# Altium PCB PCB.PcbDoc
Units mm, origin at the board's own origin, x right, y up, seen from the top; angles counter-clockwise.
Board outline 41 x 25.36 mm, 2 copper layers (TOP, BOTTOM), stack 1.586 mm thick; 37 components, 21 nets, 97 pads, 42 vias.
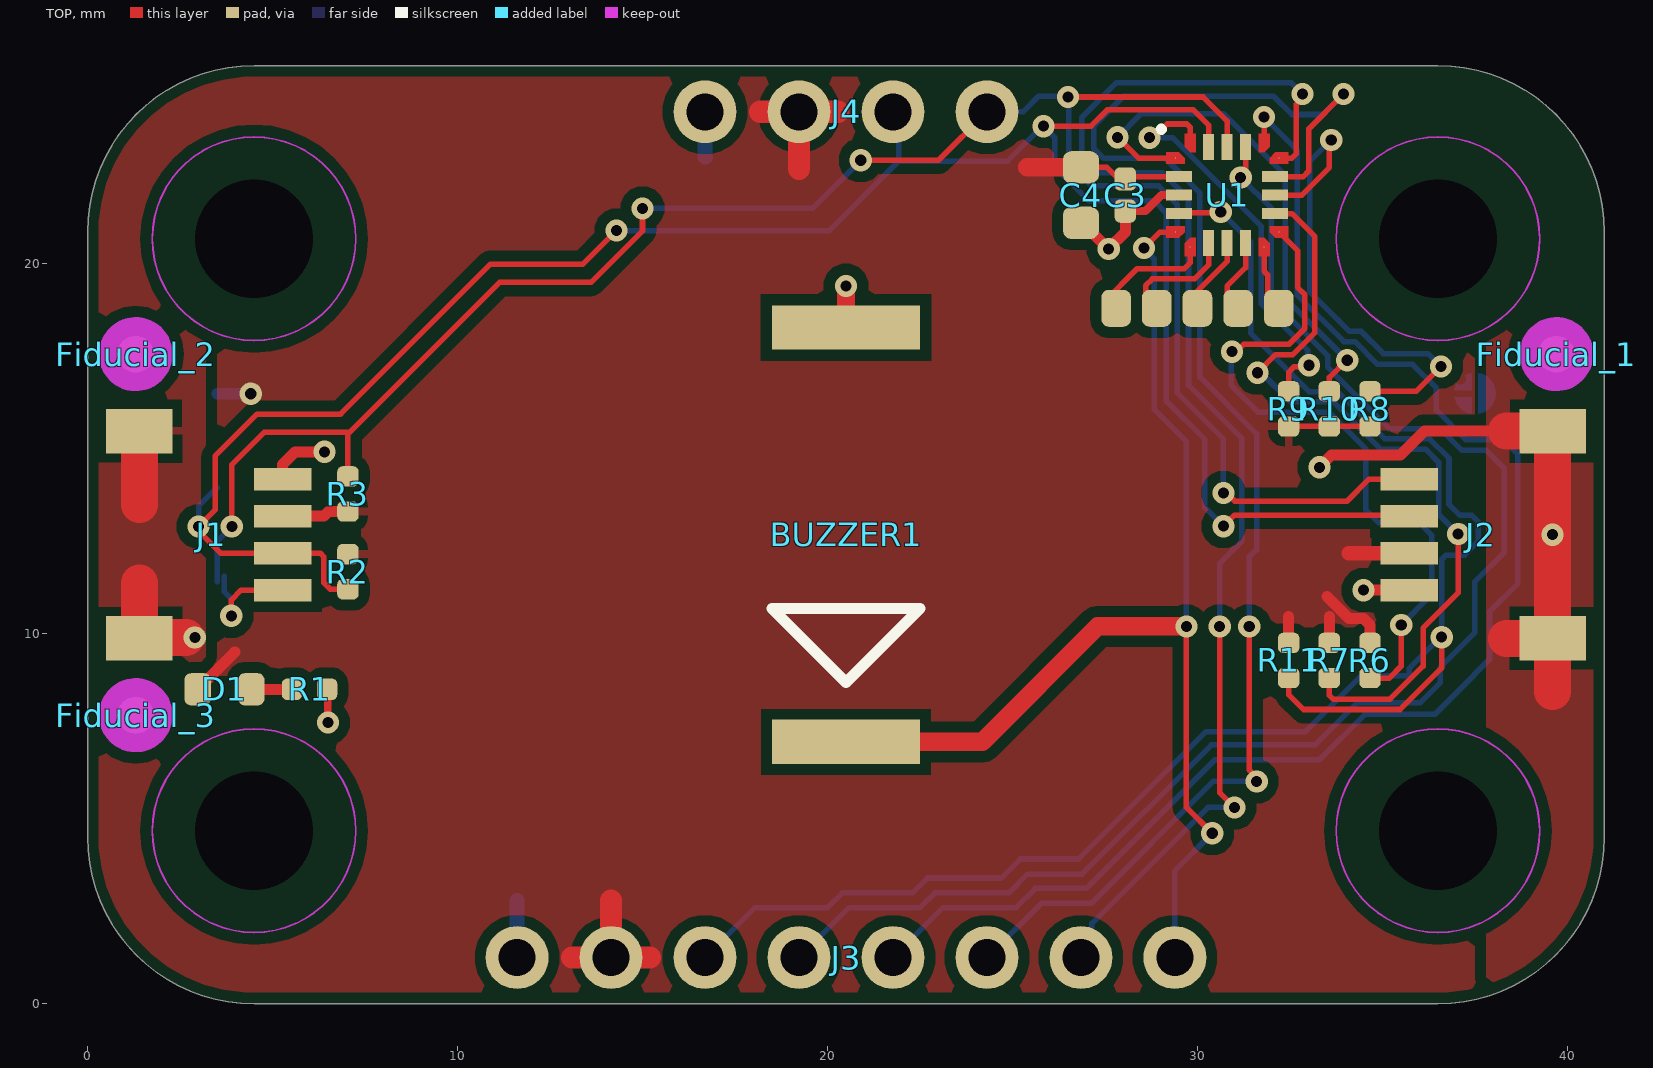
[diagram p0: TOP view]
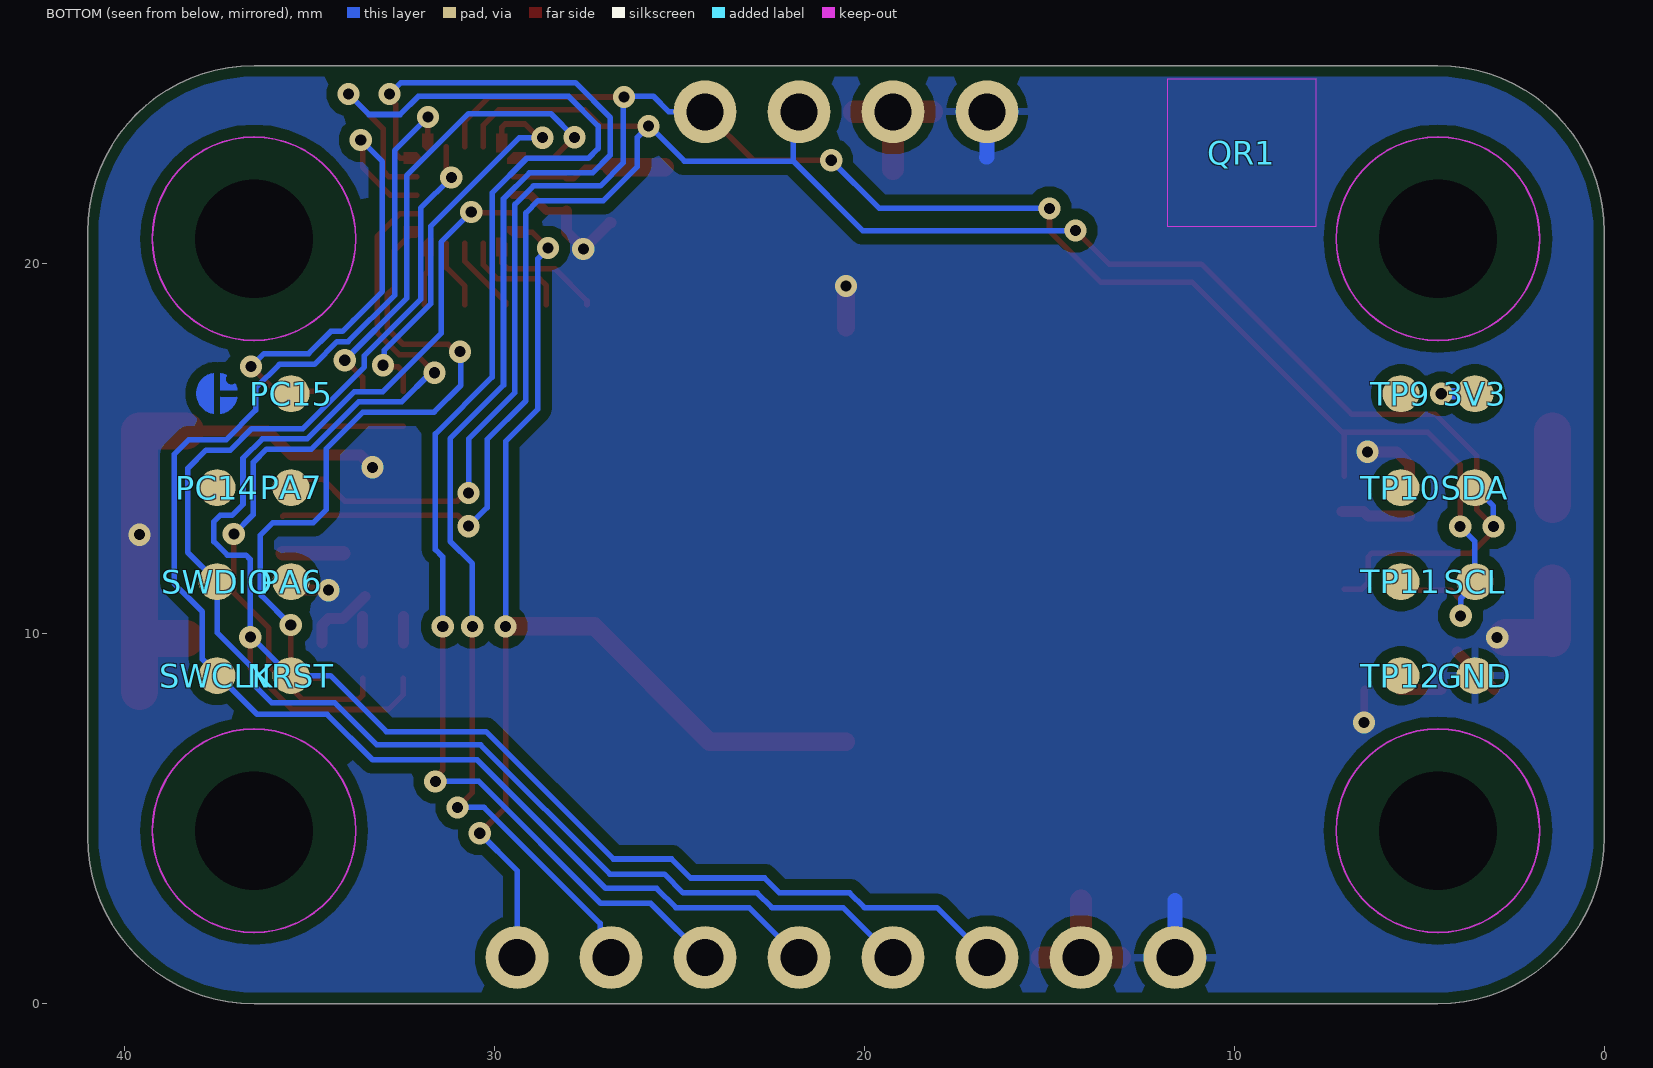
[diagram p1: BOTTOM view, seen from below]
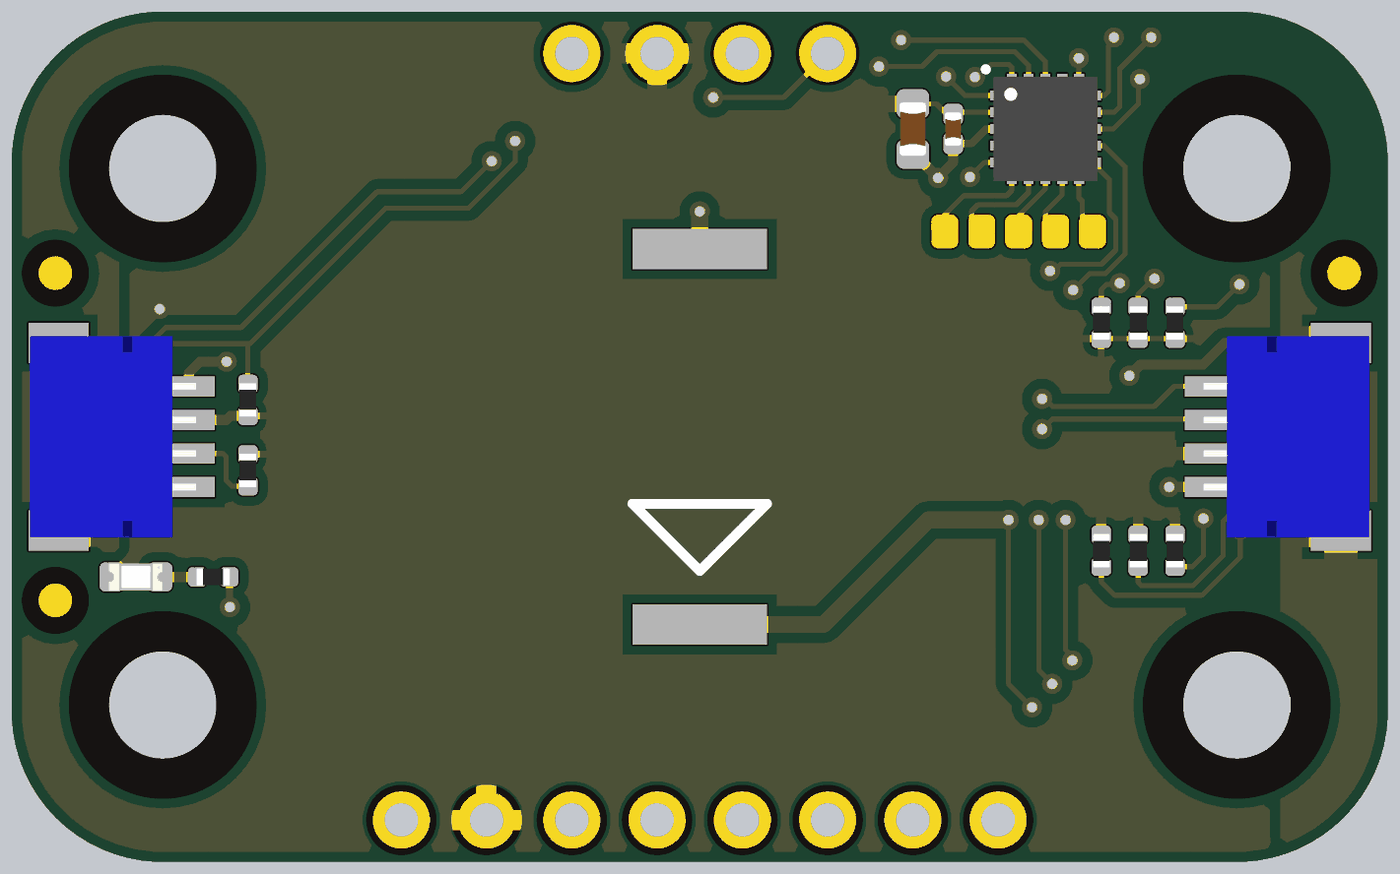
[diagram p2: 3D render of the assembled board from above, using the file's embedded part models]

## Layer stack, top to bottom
Top Solder: solder mask 0.01, Solder Resist, Dk 3.5
TOP: signal copper 0.018
Dielectric: core 1.55, FR-4, Dk 4.8
BOTTOM: signal copper 0.018
Bottom Solder: solder mask 0.01, Solder Resist, Dk 3.5

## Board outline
0,4.5 ccw(c4.5,4.5) 4.5,0 36.5,0 ccw(c36.5,4.5) 41,4.5 41,20.86 ccw(c36.5,20.86) 36.5,25.36 4.5,25.36 ccw(c4.5,20.86) 0,20.86

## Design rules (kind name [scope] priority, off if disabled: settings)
BoardOutlineClearance Mousebites [(ObjectKind = 'Pad') And (Name = 'Free-MOUSEBITE')] p1: gap=0 ignorepadtopadclearanceinfootprint=FALSE
BoardOutlineClearance Silks [(OnLayer('Top Overlay') OR OnLayer('Bottom Overlay'))] p2: gap=0 ignorepadtopadclearanceinfootprint=FALSE
BoardOutlineClearance [All] p3: gap=0.3 ignorepadtopadclearanceinfootprint=FALSE
Clearance COPPER_0.3mm [All] p1: gap=0.127 ignorepadtopadclearanceinfootprint=FALSE except(0.3: Arc-Fill Arc-Poly Arc-Region Track-Fill Track-Poly Track-Region SMDPad-Fill SMDPad-Poly SMDPad-Region THPad-Fill THPad-Poly THPad-Region Via-Fill Via-Poly Via-Region Fill-Fill Fill-Poly Fill-Region Poly-Poly Poly-Region Region-Region)
Clearance "Generic clearance 0.15mm" [All] p2: gap=0.15 ignorepadtopadclearanceinfootprint=FALSE
ComponentClearance [All] p1: gap=0.2 collisioncheckmode=3 verticalgap=0 showdistances=TRUE
DiffPairsRouting USB [InDifferentialPairClass('USB')] p1: maxlimit=0.15 minlimit=0.15 mostfreqgap=0.15 toplayer_minwidth=0.15 toplayer_maxwidth=0.21 toplayer_prefwidth=0.2 bottomlayer_minwidth=0.15 bottomlayer_maxwidth=0.21 bottomlayer_prefwidth=0.2 impedanceprofiledriven=TRUE impedanceprofileid={E6B00C31-4C8E-439C-824F-D2B2CDC26F9C} impedanceprofilevalue=90.000000 maxuncoupledlength=12.7
Height [All] p1: minheight=0 maxheight=30 prefheight=12.7
HoleSize [All] p1: absolutevalues=TRUE maxlimit=30 minlimit=0.3 maxpercent=80.000 minpercent=20.000
HoleToHoleClearance [All] p1: gap=0.25 allowstackedmicrovias=FALSE
MinimumAnnularRing [All] p1: minimumring=0.15
PlaneConnect [All] p1: pad.planeconnectstyle=Relief pad.reliefexpansion=0.508 pad.reliefentries=4 pad.reliefconductorwidth=0.254 pad.reliefairgap=0.254 via.planeconnectstyle=Direct via.reliefexpansion=0.508 via.reliefentries=4 via.reliefconductorwidth=0.254 via.reliefairgap=0.254
PolygonConnect [All] p1: thpad.connectstyle=Relief thpad.reliefconductorwidth=0.2 thpad.reliefentries=4 thpad.polygonreliefangle="90 Angle" thpad.airgapwidth=0.254 smdpad.connectstyle=Relief smdpad.reliefconductorwidth=0.2 smdpad.reliefentries=4 smdpad.polygonreliefangle="90 Angle" smdpad.airgapwidth=0.254 via.connectstyle=Direct via.reliefconductorwidth=0.254 via.reliefentries=4 via.polygonreliefangle="90 Angle" via.airgapwidth=0.254
RoomDefinition TOP [InComponentClass('TOP')] p1: confinementstyle=ConfineIn formatcopy=TRUE lockcomponents=FALSE outline 42.8,6 51.9,6 51.9,19.2 42.8,19.2
RoutingVias StandardVias [All] p1: holewidth=0.3 width=0.6 viastyle="Through Hole" minholewidth=0.3 minwidth=0.6 maxholewidth=0.3 maxwidth=0.6
SMDToCorner [All] p1: distance=39370
SilkToSilkClearance [All] p1: silktosilkclearance=0.2
SilkToSolderMaskClearance [IsPad] p1: minsilkscreentomaskgap=0.15 clearancetoexposedcopper=TRUE
SolderMaskExpansion VIAtented [IsVia] p1: expansion=0.102 istentingtop=TRUE
SolderMaskExpansion [All] p2: expansion=0.05 istentingtop=FALSE
UnConnectedPin [All] p1:
UnRoutedNet [not WithinRoom('K36')] p1: checkbadconnections=TRUE
ViasUnderSMD [All] p1: allowed=FALSE
Width StandardTraces [All] p1: maxlimit=5 minlimit=0.15 preferedwidth=0.15 minimp=50.000000 maximp=50.000000 favimp=50.000000
21 further rules are at their usual default settings.

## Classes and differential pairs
component class TOP: 3V3 BUZZER1 D1 Fiducial_1 Fiducial_2 Fiducial_3 GND J1 J2 J3 J4 NRST PA6 PA7 PC14 PC15 QR1 R1 SCL SDA SWCLK SWDIO TP9 TP10 TP11 TP12
component class U_MICROCONTROLLER: C3 C4 R2 R3 R6 R7 R8 R9 R10 R11 U1

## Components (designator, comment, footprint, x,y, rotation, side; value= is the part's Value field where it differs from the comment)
3V3 "Test point 1.00mm" TP-1.00MM 3.5,16.49 r90 bottom
BUZZER1 "PKLCS1212E4001-R1" PKLCS1212E4001-R1 20.5,12.68 r180 top
C3 "0402B104K160CT" CAP-0402 28.05,21.86 r270 top value=100nF
C4 "GRM188R61C475KAAJD" CAP-0603 26.85,21.86 r90 top value=4.7µF
D1 "HSMG-C190" LEDC1608X80N-AK 3.7,8.5 r180 top
Fiducial_1 "Fiducial mark 1mm" "Fiducial mark 1mm-Footprint-1" 39.7,17.56 r270 top
Fiducial_2 "Fiducial mark 1mm" "Fiducial mark 1mm-Footprint-1" 1.3,17.56 r270 top
Fiducial_3 "Fiducial mark 1mm" "Fiducial mark 1mm-Footprint-1" 1.3,7.8 r270 top
GND "Test point 1.00mm" TP-1.00MM 3.5,8.87 r90 bottom
J1 "SM04B-SRSS-TB(LF)(SN)" SM04B-SRSS-TB(LF)(SN)-Footprint-1 3.337,12.68 r90 top locked
J2 "SM04B-SRSS-TB(LF)(SN)" SM04B-SRSS-TB(LF)(SN)-Footprint-1 37.663,12.68 r270 top locked
J3 "HEADER TH 2.54mm VERT. 1x008POS" "PIN HEADER 2.54mm VERT. 1x8POS" 20.5,1.25 r0 top
J4 "HEADER TH 2.54mm VERT. 1x004POS" "PIN HEADER 2.54mm VERT. 1x4POS-Footprint-1" 20.5,24.11 r0 top
NRST "Test point 1.00mm" TP-1.00MM 35.5,8.87 r180 bottom
PA6 "Test point 1.00mm" TP-1.00MM 35.5,11.41 r180 bottom
PA7 "Test point 1.00mm" TP-1.00MM 35.5,13.95 r180 bottom
PC14 "Test point 1.00mm" TP-1.00MM 37.5,13.95 r180 bottom
PC15 "Test point 1.00mm" TP-1.00MM 35.5,16.49 r180 bottom
QR1 "QR CODE 4x4mm" "QR CODE 4x4mm" 9.8,23 r180 bottom
R1 "CRCW04021K00FKEDC" RES-0402 6,8.5 r180 top value=1k
R2 "RC0402FR-074K7L" RES-0402 7.039,11.68 r90 top value=4.7k
R3 "RC0402FR-074K7L" RES-0402 7.039,13.78 r270 top value=4.7k
R6 "RC0402FR-074K7L" RES-0402 34.663,9.28 r270 top value=4.7k
R7 "RC0402FR-074K7L" RES-0402 33.563,9.28 r270 top value=4.7k
R8 "RC0402FR-074K7L" RES-0402 34.663,16.08 r90 top value=4.7k
R9 "RC0402FR-074K7L" RES-0402 32.463,16.08 r90 top value=4.7k
R10 "RC0402FR-074K7L" RES-0402 33.563,16.08 r90 top value=4.7k
R11 "RC0402FR-074K7L" RES-0402 32.463,9.28 r270 top value=4.7k
SCL "Test point 1.00mm" TP-1.00MM 3.5,11.41 r90 bottom
SDA "Test point 1.00mm" TP-1.00MM 3.5,13.95 r90 bottom
SWCLK "Test point 1.00mm" TP-1.00MM 37.5,8.87 r180 bottom
SWDIO "Test point 1.00mm" TP-1.00MM 37.5,11.41 r180 bottom
TP9 "Test point 1.00mm" TP-1.00MM 5.5,16.49 r0 bottom
TP10 "Test point 1.00mm" TP-1.00MM 5.5,13.95 r0 bottom
TP11 "Test point 1.00mm" TP-1.00MM 5.5,11.41 r0 bottom
TP12 "Test point 1.00mm" TP-1.00MM 5.5,8.87 r0 bottom
U1 "STM32C011F4U6TR" UFQFPN20 30.8,21.86 r0 top

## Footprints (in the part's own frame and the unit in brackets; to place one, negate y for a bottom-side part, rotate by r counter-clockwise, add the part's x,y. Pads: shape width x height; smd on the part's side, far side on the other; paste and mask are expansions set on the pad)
CAP-0402 [mm] "Chip Capacitor, 2-Leads, Body  0402 (in) 1005 (mm), IPC Medium Density"
  rrect52% 0.63x0.58 smd mask+0.05: 1(-0.435,0) 2(0.435,0)
  body extent -0.5,-0.25 0.5,0.25, height 0.5
CAP-0603 [mm] "Chip Capacitor, Body 0603 imperial,1.6x0.8mm, IPC High Density"
  rrect51% 0.87x0.97 smd mask+0.05: 1(-0.75,0) 2(0.75,0)
  body extent -0.8,-0.4 0.8,0.4, height 0.8
"Fiducial mark 1mm-Footprint-1" [mm]
  round 1 smd paste-10 mask+0.5: 1(0,0)
  TOP keep-out circle w1: c0,0 r0.5
LEDC1608X80N-AK [mm]
  rrect50% 0.72x0.87 smd: A(0.725,0) C(-0.725,0)
  body extent -0.8,-0.4 0.8,0.4, height 0.79
"PIN HEADER 2.54mm VERT. 1x4POS-Footprint-1" [mm]
  round 1.7 hole 1 mask+0.1: 1(-3.81,0) 2(-1.27,0) 3(1.27,0) 4(3.81,0)
"PIN HEADER 2.54mm VERT. 1x8POS" [mm]
  round 1.7 hole 1 mask+0.2: 1(-8.89,0) 2(-6.35,0) 3(-3.81,0) 4(-1.27,0) 5(1.27,0) 6(3.81,0) 7(6.35,0) 8(8.89,0)
PKLCS1212E4001-R1 [mm]
  rect 4x1.2 smd: 1(0,5.6) 2(0,-5.6)
  silkscreen extent -2,2 2,4, body extent -6,-6 6,6, height 3.03
"QR CODE 4x4mm" [mm]
  TOP keep-out region: -2,2 2,2 2,-2 -2,-2
RES-0402 [mm] "Chip Resistor, 2-Leads, Body  0402 (in) 1005 (mm), IPC Medium Density"
  rrect51% 0.55x0.58 smd mask+0.05: 1(-0.475,0) 2(0.475,0)
  body extent -0.5,-0.25 0.5,0.25, height 0.34
SM04B-SRSS-TB(LF)(SN)-Footprint-1 [mm]
  rect 0.6x1.55 smd mask+0.05: 1(1.5,-1.937) 2(0.5,-1.937) 3(-0.5,-1.937) 4(-1.5,-1.937)
  rect 1.2x1.8 smd mask+0.05: FIX(-2.8,1.938) FIX(2.8,1.938)
  body extent -3,-2.16 3,2.8, height 2.98
TP-1.00MM [mm]
  rrect100% 1x1 smd paste-2.54: X(0,0)
UFQFPN20 [mm] "QFN, 20-Leads, Body 3.00x3.00mm, Pitch 0.50mm, IPC Medium Density"
  round 0.025 smd mask+0.05: 1(-1.4,1) 5(-1.4,-1) 6(-1,-1.4) 10(1,-1.4) 11(1.4,-1) 15(1.4,1) 16(1,1.4) 20(-1,1.4)
  rect 0.7x0.3 smd mask+0.05: 2(-1.3,0.5) 3(-1.3,0) 4(-1.3,-0.5) 12(1.3,-0.5) 13(1.3,0) 14(1.3,0.5)
  rect 0.3x0.7 smd mask+0.05: 7(-0.5,-1.3) 8(0,-1.3) 9(0.5,-1.3) 17(0.5,1.3) 18(0,1.3) 19(-0.5,1.3)
  TOP region: -1.3,-1.15 -1.15,-1 -1.15,-0.85 -1.65,-0.85 -1.65,-1.15
  TOP region: -0.85,-1.65 -1.15,-1.65 -1.15,-1.3 -1,-1.15 -0.85,-1.15
  TOP region: 1.15,-1.65 0.85,-1.65 0.85,-1.15 1,-1.15 1.15,-1.3
  TOP region: 1.65,1.15 1.65,0.85 1.15,0.85 1.15,1 1.3,1.15
  TOP region: 1,1.15 0.85,1.15 0.85,1.65 1.15,1.65 1.15,1.3
  TOP region: -1.15,1 -1.15,0.85 -1.65,0.85 -1.65,1.15 -1.3,1.15
  TOP region: -1.15,1.3 -1,1.15 -0.85,1.15 -0.85,1.65 -1.15,1.65
  TOP region: 1.65,-0.85 1.65,-1.15 1.3,-1.15 1.15,-1 1.15,-0.85
  silkscreen extent -1.8,1.75 -1.75,1.8, body extent -1.55,-1.55 1.55,1.55, height 0.6

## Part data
3V3 GND NRST PA6 PA7 PC14 PC15 SCL SDA SWCLK SWDIO TP9 TP10 TP11 TP12: library part UT0013-A.6, Manufacturer="This is not a component"
BUZZER1: library part S0056-A.2, "BUZZER VDD max 12.5Vpp, max 100mA, min 75dB at 4kHz 12x12x3mm", Manufacturer=Murata
C3: library part C0012-A.15, "CAP CHIP 0402 100nF 10% 16V X7R", Case Code (Imperial)=0402, Dielectric=X7R, Manufacturer=Walsin, Tolerance=10%, Voltage=16V
C4: library part C0054-A.16, "CAP CHIP 0603 4.7uF 10% 16V X5R", Case Code (Imperial)=0603, Dielectric=X5R, Manufacturer=Murata, Manufacturer 3="Samsung Electro-Mechanics", Part number 2=GRM188R61C475KE11D, Part number 3=CL10A475KO8NNNC, Tolerance=10%, Voltage=16V
D1: library part L0009-A.5, "LED SMD 0603 GREEN/568 15mcd 120^", Manufacturer=Broadcom
Fiducial_1 Fiducial_2 Fiducial_3: library part UT0023-A.7, "Fiducial mark 1mm clearance 2mm"
J1 J2: library part J0005-A.2, "CONN JST 4POS SIDE 1MM TIN QWIIC", Manufacturer=JST
J3: library part J0171-A.3
J4: library part J0162-A.5
QR1: library part QR-0001-A.2, "QR CODE 4x4mm on layer 34 (This is not a component)", Manufacturer="This is not a component"
R1: library part R0007-A.24, "RES CHIP 0402 1k 1% 1/16W", Case Code (Imperial)=0402, Manufacturer=Vishay, Power=62.5mW, Temperature Coefficient=100ppm, Tolerance=1%
R2 R3 R6 R7 R8 R9 R10 R11: library part R0013-A.24, "RES CHIP 0402 4k7 1% 1/16W", Case Code (Imperial)=0402, Manufacturer=YAGEO, Power=62.5mW, Temperature Coefficient=200ppm, Tolerance=1%
U1: library part U0363-A.3, "IC Cortex M0, 32b MCU, 32KB Flash, 6KB RAM, VDD 2-3.6V, -40°C to 85°C, QFN20 3x3mm", Manufacturer="ST Microelectronics"

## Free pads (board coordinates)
  rrect50% 0.8x1 smd paste-2539.97: 3V8(28.9,18.8) 3V9(27.8,18.8) 3V9(30,18.8) 3V10(31.1,18.8) 3V10(32.2,18.8)
  round 3 hole 3.2 unplated paste-2539.97 mask+1.3: MH(4.5,4.68) MH(4.5,20.68) MH(36.5,4.68) MH(36.5,20.68)

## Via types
v1: diameter 0.6, hole 0.3, TOP to BOTTOM, tented both sides, 42 vias

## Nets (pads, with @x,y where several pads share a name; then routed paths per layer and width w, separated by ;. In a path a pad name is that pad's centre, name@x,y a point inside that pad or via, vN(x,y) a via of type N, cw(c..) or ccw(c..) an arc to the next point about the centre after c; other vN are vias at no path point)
+3V3: 3V3.X C3.1 C4.2 D1.A J1.2 J2.2 J3.2 J4.2 R2.2 R3.2 R6.1 R7.1 R8.1 R9.1 R10.1 R11.1 U1.2 | length 23
  TOP w0.15: C4.2 27.55,22.61 27.865,22.295 C3.1 28.115,22.36 U1.2 ; R9.1 R10.1 R8.1
  TOP w0.3: D1.A 3.98,9.505 ; J1.2 6.389,13.18 6.514,13.305 R3.2@7.089,13.305 ; R11.1 32.463,10.463 ; 33.5,11.01 34.1,10.41 34.487,10.41 34.663,10.234 R6.1 ; R7.1 33.563,10.463
  TOP w0.4: 34.088,12.18 J2.2
  TOP w0.5: 25.4,22.61 C4.2
  TOP w0.6: 13.1,1.25 J3.2 ; 14.15,2.79 J3.2 ; 15.2,1.25 J3.2 ; 18.18,24.11 J4.2 ; 19.23,22.57 J4.2 ; 20.28,24.11 J4.2
  BOTTOM w0.3: 3V3.X v1(4.41,16.49)
GND: BUZZER1.2 C3.2 C4.1 GND.X J1.1 J1.FIX J2.1 J2.FIX J3.1 J4.1 R1.1 U1.3 | length 34.1
  TOP w0.2: R1.1 6.488,8.488 6.488,7.612 v1(6.5,7.6)
  TOP w0.22: C3.2 28.592,21.425 29.027,21.86 U1.3
  TOP w0.3: J1.1 5.275,14.58 5.614,14.919 v1(6.404,14.919) ; C4.1 26.895,21.11 v1@27.6,20.405 ; v1(27.6,20.4) v1@27.6,20.405 ; C3.2 28.05,20.866 27.6,20.416 v1@27.6,20.405 ; v1(33.3,14.5) 33.628,14.828 35.486,14.828 36.138,15.48 J2.FIX@39.601,15.48 ; v1(34.488,11.18) J2.1
  TOP w0.5: J1.FIX@1.399,9.88 1.419,9.9 v1(2.9,9.9) ; BUZZER1.2 v1(20.5,19.4)
  TOP w1: J1.FIX@1.399,9.88 1.399,11.379 ; 1.399,13.499 J1.FIX@1.399,15.48 ; J1.FIX@1.419,9.9 v1@2.667,9.9 ; 38.353,9.88 J2.FIX@39.601,9.88 ; 38.353,15.48 39.601,15.48 J2.FIX@39.601,9.88 ; 39.601,8.443 J2.FIX@39.601,9.88
  BOTTOM w0.4: J3.1 11.61,2.79 ; J4.1 16.69,22.89 16.7,22.88
  other v1: 39.596,12.68
NetD1_C: D1.C R1.2 | length 1.1
  TOP w0.3: D1.C R1.2
NetU1_6: pad.3V9@27.8,18.8 U1.6 | length 3.3
  TOP w0.15: pad.3V9@27.5,18.9 27.5,19 28.373,19.873 29.644,19.873 29.8,20.028 U1.6
NetU1_7: pad.3V8 U1.7 | length 3
  TOP w0.15: pad.3V8@28.6,18.9 28.6,19.415 28.781,19.596 29.925,19.596 30.3,19.971 U1.7
NetU1_8: pad.3V9@30,18.8 U1.8 | length 2.1
  TOP w0.15: pad.3V9@29.7,18.9 29.7,18.968 30.8,20.068 U1.8
NetU1_9: pad.3V10@31.1,18.8 U1.9 | length 1.9
  TOP w0.15: pad.3V10@30.8,18.9 30.8,19.4 31.3,19.9 U1.9
NetU1_10: pad.3V10@32.2,18.8 U1.10 | length 1.6
  TOP w0.15: U1.10 31.8,19.8 31.9,19.7 pad.3V10@31.9,18.9
PA0_1: BUZZER1.1 J3.8 U1.5 | length 31.9
  TOP w0.15: v1(28.552,20.428) 28.984,20.86 U1.5 ; v1(29.7,10.2) 29.7,5.31 v1(30.4,4.61)
  TOP w0.5: BUZZER1.1 24.18,7.08 27.3,10.2 v1(29.7,10.2)
  BOTTOM w0.15: v1(28.552,20.428) 28.552,20.413 28.828,20.138 28.828,16.072 29.7,15.2 v1(29.7,10.2) ; J3.8 29.39,3.6 v1(30.4,4.61)
PA6_2: R6.2 U1.11 | length 19
  TOP w0.15: v1(30.937,17.626) 31.053,17.626 31.249,17.823 32.466,17.823 32.899,18.255 32.899,19.17 32.705,19.364 32.705,20.355 U1.11 ; R6.2 35.184,8.805 35.508,9.128 v1(35.508,10.241)
  BOTTOM w0.15: v1(30.937,17.626) 30.913,17.602 30.913,16.717 31.636,15.994 33.558,15.994 34.547,15.005 34.547,13.356 34.903,13 36,13 36.33,12.67 36.33,11.13 36.3,11.1 36.3,11.033 v1(35.508,10.241)
PA7_2: R7.2 U1.12 | length 21.4
  TOP w0.15: v1(31.624,17.056) 32.113,17.546 32.581,17.546 33.176,18.141 33.176,20.734 32.55,21.36 U1.12 ; R7.2 33.563,8.337 33.665,8.234 35.203,8.234 36.098,9.129 36.098,10.158 37.054,11.114 37.054,12.689 v1(37.046,12.697)
  BOTTOM w0.15: v1(31.624,17.056) 31.723,17.056 32.509,16.271 33.673,16.271 34.952,14.992 36.162,14.992 36.521,14.632 36.521,13.222 v1(37.046,12.697)
PA8_2: R8.2 U1.13 | length 13.5
  TOP w0.15: U1.13 32.822,21.86 33.567,22.605 33.567,23.3 v1(33.615,23.347) ; R8.2 35.908,16.555 v1(36.579,17.226)
  BOTTOM w0.15: v1(33.615,23.347) 33.029,22.762 33.029,19.258 33.816,18.471 34.114,18.173 34.427,18.173 35.027,17.573 36.231,17.573 v1(36.579,17.226)
PA9_USART1_TX_1: J3.6 U1.14 | length 40.9
  TOP w0.15: v1(31.4,10.2) 31.4,6.323 31.6,6.123 v1(31.6,6.01) ; U1.14 32.86,22.36 33.008,22.508 33.008,23.648 v1(33.95,24.59)
  BOTTOM w0.15: J3.6 25.778,2.718 27.133,2.718 30.425,6.01 v1(31.6,6.01) ; v1(31.4,10.2) 31.4,12.078 31.6,12.278 31.6,15.404 30.067,16.938 30.067,21.917 29.13,22.854 27.463,22.854 27.199,23.118 27.199,23.73 27.998,24.53 32.058,24.53 32.551,24.037 33.397,24.037 v1(33.95,24.59)
PA10_USART1_RX_1: J3.7 U1.15 | length 36.7
  TOP w0.15: v1(30.6,10.2) 30.6,5.71 v1(31,5.31) ; U1.15 32.554,22.86 32.671,22.977 32.671,24.312 32.841,24.482 v1(32.841,24.591)
  BOTTOM w0.15: J3.7 27.147,1.547 27.147,2.172 30.285,5.31 v1(31,5.31) ; v1(30.6,10.2) 30.6,11.9 31.202,12.502 31.202,15.276 29.757,16.72 29.757,21.759 29.056,22.46 27.35,22.46 26.871,22.939 26.871,23.956 27.816,24.9 32.531,24.9 v1(32.841,24.591)
PA13_SWDIO_1: J3.5 SWCLK.X U1.16 | length 39.4
  TOP w0.15: v1@31.744,24.019 v1(31.795,23.968) 31.8,23.963 U1.16
  BOTTOM w0.15: J3.5 23.12,2.6 25.1,2.6 25.618,3.118 26.993,3.118 30.471,6.596 33.296,6.596 34.523,7.823 36.413,7.823 37.48,8.89 37.48,8.899 37.9,9.319 37.9,10.6 38.662,11.362 38.662,14.848 38.266,15.244 37.256,15.244 36.456,16.044 36.456,16.639 35.812,17.282 34.869,17.282 34.255,17.896 33.955,17.896 32.702,19.149 32.702,23.061 v1(31.795,23.968)
PA14_SWCLK_BOOT0_1: J3.4 SWDIO.X U1.17 | length 39.8
  TOP w0.15: v1(31.167,22.336) 31.167,22.429 31.3,22.562 U1.17
  BOTTOM w0.15: J3.4 20.58,2.6 22.5,2.6 22.9,3 24.9,3 25.407,3.507 26.881,3.507 30.375,7 33.181,7 34.324,8.143 36.027,8.143 36.557,8.673 36.557,9.089 37.5,10.032 SWDIO.X 38.291,12.201 38.291,14.474 37.799,14.967 37.141,14.967 36.563,15.546 35.181,15.546 34.517,16.21 34.517,16.214 33.516,17.216 33.516,17.52 31.998,19.038 31.998,21.506 v1(31.167,22.336)
PC14_2: R9.2 U1.20 | length 11.2
  TOP w0.15: v1(28.7,23.41) 28.808,23.41 29.178,23.781 29.712,23.781 29.8,23.693 U1.20 ; R9.2 32.463,17.068 32.614,17.219 32.973,17.219 v1(33.014,17.259)
  BOTTOM w0.15: v1(28.7,23.41) 29.33,23.41 31.721,21.02 31.721,18.924 32.985,17.659 32.985,17.288 v1(33.014,17.259)
PC15_2: R10.2 U1.1 | length 14
  TOP w0.15: v1@27.85,23.42 28.41,22.86 U1.1 ; R10.2 33.563,16.93 34.027,17.394 v1(34.047,17.394)
  BOTTOM w0.15: v1(27.84,23.42) 28.48,24.06 30.698,24.06 32.375,22.383 32.375,19.066 v1(34.047,17.394)
PF2_N\R\S\T\_1: J3.3 NRST.X R11.2 U1.4 | length 47.2
  TOP w0.15: U1.4 29.52,21.38 30.61,21.38 v1(30.63,21.4) ; R11.2 32.463,8.359 32.866,7.955 35.479,7.955 36.6,9.076 v1(36.6,9.91)
  BOTTOM w0.15: J3.3 18.04,2.6 20,2.6 20.4,3 22.3,3 22.7,3.4 24.7,3.4 25.214,3.914 26.788,3.914 30.233,7.359 32.923,7.359 34.434,8.87 NRST.X 35.722,8.87 35.722,9.062 36.57,9.91 v1(36.6,9.91) 36.6,10.941 36.607,10.948 36.607,12.016 36.718,12.127 37.22,12.127 37.587,12.494 37.587,13.032 37.417,13.202 37.097,13.202 36.798,13.501 36.798,14.747 36.277,15.269 35.067,15.269 33.788,16.548 33.015,16.548 31.444,18.119 31.444,20.587 v1(30.63,21.4)
SCL_1: J1.4 J2.4 J4.4 R3.1 SCL.X U1.18 | length 58.8
  TOP w0.15: v1(3.886,10.486) 3.886,10.916 4.15,11.18 J1.4 ; v1(3.9,12.9) 3.9,14.573 4.78,15.453 7.089,15.453 11.137,19.5 13.61,19.5 15,20.89 v1(15,21.5) ; R3.1 7.039,15.453 ; v1(20.9,22.8) 23,22.8 J4.4 ; v1(26.5,24.51) 30.151,24.51 30.8,23.861 U1.18 ; v1(30.7,13.81) 30.786,13.81 31.013,13.583 34.041,13.583 34.638,14.18 J2.4
  BOTTOM w0.15: SCL.X 3.5,12.5 v1(3.9,12.9) ; SCL.X@3.694,11.557 3.694,11.14 3.886,10.948 v1(3.886,10.486) ; v1(15,21.5) 19.6,21.5 v1(20.9,22.8) ; J4.4 25.288,24.11 25.71,24.532 26.478,24.532 v1(26.5,24.51) 26.516,24.494 26.516,22.735 27.141,22.11 28.947,22.11 29.452,21.605 29.452,16.518 30.7,15.27 v1(30.7,13.81)
SDA_1: J1.3 J2.3 J4.3 R2.1 SDA.X U1.19 | length 60.5
  TOP w0.15: R2.1 6.564,11.205 6.389,11.38 6.389,12.08 6.289,12.18 J1.3 3.598,12.18 3.186,12.592 3,12.778 v1(3,12.9) 3.448,13.348 3.448,14.801 4.585,15.938 6.838,15.938 10.891,19.991 13.391,19.991 v1(14.3,20.9) ; v1(25.838,23.722) 27.122,23.722 27.56,24.16 29.888,24.16 30.3,23.748 U1.19 ; v1(30.7,12.91) 31,13.21 35.696,13.21 J2.3
  BOTTOM w0.15: v1(3,12.9) 3,13.45 SDA.X ; v1(14.3,20.9) 20.05,20.9 21.926,22.776 ; J4.3 21.926,23.954 21.926,22.776 ; v1(30.7,12.91) 30.198,13.412 30.198,15.257 29.155,16.3 29.155,21.375 28.819,21.71 27.058,21.71 26.138,22.629 26.138,23.422 v1(25.838,23.722) 25.814,23.722 24.869,22.776 21.926,22.776
pads on no net: Fiducial_1.1 Fiducial_2.1 Fiducial_3.1 PA6.X PA7.X PC14.X PC15.X TP9.X TP10.X TP11.X TP12.X

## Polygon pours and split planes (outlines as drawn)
+3V3 on TOP "NONET_L04_P-001" (solid, remove dead copper, pour order 6): 0,4.5 ccw(c4.5,4.5) 4.5,0 36.5,0 ccw(c36.5,4.5) 41,4.5 41,20.86 ccw(c36.5,20.86) 36.5,25.36 4.5,25.36 ccw(c4.5,20.86) 0,20.86
GND on TOP "NONET_L04_P-001" (solid, remove dead copper, pour order 5): 41,25.36 41,0 37.8,0 37.8,25.36
GND on TOP "NONET_L04_P-001" (solid, remove dead copper, pour order 4): 0,25.36 0,0 3.2,0 3.2,25.36
GND on BOTTOM "NONET_L04_P-001" (solid, remove dead copper, pour order 7): 0,4.5 ccw(c4.5,4.5) 4.5,0 36.5,0 ccw(c36.5,4.5) 41,4.5 41,20.86 ccw(c36.5,20.86) 36.5,25.36 4.5,25.36 ccw(c4.5,20.86) 0,20.86

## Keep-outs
Keep-Out Layer:
  circle w0.05: c36.5,4.68 r2.75
  circle w0.05: c36.5,20.68 r2.75
  circle w0.05: c4.5,4.68 r2.75
  circle w0.05: c4.5,20.68 r2.75

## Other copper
BOTTOM:
  region: 37.256,16.811 37.256,16.815 37.251,16.815 37.251,16.82 37.256,16.82 37.256,16.824 37.26,16.824 37.26,16.829 37.265,16.829 37.265,16.939 37.26,16.939 37.26,16.943 37.256,16.943 37.256,16.948 37.251,16.948 37.251,16.965 37.243,16.965 37.243,16.97 37.238,16.97 37.238,16.974 37.234,16.974 37.234,16.983 37.238,16.983 37.238,16.987 37.243,16.987 37.243,16.992 37.247,16.992 37.247,16.996 37.265,16.996 37.265,17.005 37.282,17.005 37.282,17.009 37.287,17.009 37.287,17.018 37.318,17.018 37.318,17.027 37.349,17.027 37.349,17.036 37.353,17.036 37.353,17.04 37.362,17.04 37.362,17.036 37.388,17.036 37.388,17.04 37.393,17.04 37.393,17.049 37.41,17.049 37.41,17.04 37.415,17.04 37.415,17.036 37.41,17.036 37.41,16.595 37.415,16.595 37.415,16.591 37.41,16.591 37.41,16.582 36.947,16.582 36.947,16.595 36.956,16.595 36.956,16.643 36.96,16.643 36.96,16.648 36.965,16.648 36.965,16.652 36.969,16.652 36.969,16.679 36.978,16.679 36.978,16.71 36.987,16.71 36.987,16.727 36.991,16.727 36.991,16.732 37,16.732 37,16.749 37.005,16.749 37.005,16.754 37.009,16.754 37.009,16.763 37.022,16.763 37.022,16.754 37.04,16.754 37.04,16.745 37.044,16.745 37.044,16.74 37.062,16.74 37.062,16.736 37.066,16.736 37.066,16.732 37.159,16.732 37.159,16.74 37.185,16.74 37.185,16.745 37.19,16.745 37.19,16.749 37.194,16.749 37.194,16.754 37.199,16.754 37.199,16.758 37.203,16.758 37.203,16.763 37.207,16.763 37.207,16.767 37.212,16.767 37.212,16.771 37.216,16.771 37.216,16.776 37.221,16.776 37.221,16.78 37.225,16.78 37.225,16.785 37.229,16.785 37.229,16.789 37.234,16.789 37.234,16.793 37.238,16.793 37.238,16.798 37.243,16.798 37.243,16.802 37.247,16.802 37.247,16.807 37.251,16.807 37.251,16.811
  region: 37.296,15.978 37.291,15.978 37.291,15.982 37.287,15.982 37.287,15.986 37.282,15.986 37.282,15.991 37.256,15.991 37.256,15.995 37.251,15.995 37.251,16 37.234,16 37.234,16.008 37.229,16.008 37.229,16.013 37.225,16.013 37.225,16.017 37.221,16.017 37.221,16.022 37.203,16.022 37.203,16.026 37.199,16.026 37.199,16.03 37.194,16.03 37.194,16.035 37.19,16.035 37.19,16.03 37.185,16.03 37.185,16.035 37.181,16.035 37.181,16.039 37.177,16.039 37.177,16.044 37.172,16.044 37.172,16.048 37.168,16.048 37.168,16.052 37.163,16.052 37.163,16.057 37.159,16.057 37.159,16.061 37.154,16.061 37.154,16.066 37.137,16.066 37.137,16.075 37.128,16.075 37.128,16.083 37.119,16.083 37.119,16.088 37.115,16.088 37.115,16.097 37.106,16.097 37.106,16.105 37.097,16.105 37.097,16.11 37.093,16.11 37.093,16.119 37.084,16.119 37.084,16.127 37.075,16.127 37.075,16.145 37.071,16.145 37.071,16.15 37.066,16.15 37.066,16.154 37.062,16.154 37.062,16.158 37.057,16.158 37.057,16.163 37.053,16.163 37.053,16.167 37.049,16.167 37.049,16.172 37.044,16.172 37.044,16.176 37.04,16.176 37.04,16.189 37.035,16.189 37.035,16.194 37.031,16.194 37.031,16.198 37.027,16.198 37.027,16.202 37.022,16.202 37.022,16.22 37.018,16.22 37.018,16.224 37.009,16.224 37.009,16.242 37.005,16.242 37.005,16.247 37,16.247 37,16.264 36.991,16.264 36.991,16.269 36.987,16.269 36.987,16.277 36.991,16.277 36.991,16.282 36.987,16.282 36.987,16.286 36.982,16.286 36.982,16.291 36.978,16.291 36.978,16.317 36.969,16.317 36.969,16.348 36.96,16.348 36.96,16.352 36.956,16.352 36.956,16.401 36.965,16.401 36.965,16.405 36.974,16.405 36.974,16.401 37.397,16.401 37.397,16.405 37.406,16.405 37.406,16.401 37.41,16.401 37.41,16.396 37.415,16.396 37.415,16.388 37.41,16.388 37.41,15.96 37.415,15.96 37.415,15.955 37.41,15.955 37.41,15.947 37.384,15.947 37.384,15.951 37.379,15.951 37.379,15.955 37.375,15.955 37.375,15.96 37.34,15.96 37.34,15.964 37.335,15.964 37.335,15.969 37.309,15.969 37.309,15.973 37.304,15.973 37.304,15.978 37.3,15.978 37.3,15.982 37.296,15.982
  region: 283 vertices and 0 holes, not listed, extent 37.591,15.947 38.059,17.049

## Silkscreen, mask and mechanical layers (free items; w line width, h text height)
Route Tool Path:
  lines w2: -1,8.498 -1,16.86 ; 42,4.5 cw(c36.5,4.5) 36.5,-1 ; 42,8.498 42,16.86 ; -1,4.498 cw(c0,4.5) -1,4.5 ccw(c4.5,4.5) -1,4.498 ; -1,4.498 ccw(c4.5,4.5) 4.498,-1 ; -1,20.86 cw(c4.5,20.86) 4.5,26.36 ; -1,20.86 -1,20.86 ; 4.498,-1 ccw(c4.5,0) 4.5,-1 ; 4.498,-1 ccw(c4.5,4.5) 4.5,-1 ; 4.5,-1 36.5,-1 ; 4.5,26.36 4.5,26.36 ; 4.5,26.36 36.5,26.36 ; 36.5,-1 36.5,-1 ; 36.5,26.36 cw(c36.5,25.36) 36.502,26.36 ; 36.5,26.36 cw(c36.5,20.86) 36.502,26.36 ; 36.502,26.36 cw(c36.5,20.86) 42,20.863 ; 42,20.863 cw(c36.5,20.86) 42,20.86 ccw(c41,20.86) 42,20.863
Mechanical 33:
  lines w0.05: 8.44,1.25 9.07,1.25 ; 9.07,0.62 9.07,1.25 ; 9.07,1.88 9.07,1.25 ; 9.7,1.25 9.07,1.25 ; 10.98,1.25 11.61,1.25 ; 11.61,0.62 11.61,1.25 ; 11.61,1.88 11.61,1.25 ; 12.24,1.25 11.61,1.25 ; 13.52,1.25 14.15,1.25 ; 14.15,0.62 14.15,1.25 ; 14.15,1.88 14.15,1.25 ; 14.78,1.25 14.15,1.25 ; 16.06,1.25 16.69,1.25 ; 16.06,24.11 16.69,24.11 ; 16.69,0.62 16.69,1.25 ; 16.69,1.88 16.69,1.25 ; 16.69,23.48 16.69,24.11 ; 16.69,24.74 16.69,24.11 ; 17.32,1.25 16.69,1.25 ; 17.32,24.11 16.69,24.11 ; 18.6,1.25 19.23,1.25 ; 18.6,24.11 19.23,24.11 ; 19.23,0.62 19.23,1.25 ; 19.23,1.88 19.23,1.25 ; 19.23,23.48 19.23,24.11 ; 19.23,24.74 19.23,24.11 ; 19.86,1.25 19.23,1.25 ; 19.86,24.11 19.23,24.11 ; 21.14,1.25 21.77,1.25 ; 21.14,24.11 21.77,24.11 ; 21.77,0.62 21.77,1.25 ; 21.77,1.88 21.77,1.25 ; 21.77,23.48 21.77,24.11 ; 21.77,24.74 21.77,24.11 ; 22.4,1.25 21.77,1.25 ; 22.4,24.11 21.77,24.11 ; 23.68,1.25 24.31,1.25 ; 23.68,24.11 24.31,24.11 ; 24.31,0.62 24.31,1.25 ; 24.31,1.88 24.31,1.25 ; 24.31,23.48 24.31,24.11 ; 24.31,24.74 24.31,24.11 ; 24.94,1.25 24.31,1.25 ; 24.94,24.11 24.31,24.11 ; 26.22,1.25 26.85,1.25 ; 26.85,0.62 26.85,1.25 ; 26.85,1.88 26.85,1.25 ; 27.48,1.25 26.85,1.25 ; 28.76,1.25 29.39,1.25 ; 29.39,0.62 29.39,1.25 ; 29.39,1.88 29.39,1.25 ; 30.02,1.25 29.39,1.25 ; 31.3,1.25 31.93,1.25 ; 31.93,0.62 31.93,1.25 ; 31.93,1.88 31.93,1.25 ; 32.56,1.25 31.93,1.25
Mechanical 66:
  circle w0.05: c36.5,4.68 r2.85
  circle w0.05: c36.5,20.68 r2.85
  circle w0.05: c4.5,20.68 r2.85
  circle w0.05: c4.5,4.68 r2.85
